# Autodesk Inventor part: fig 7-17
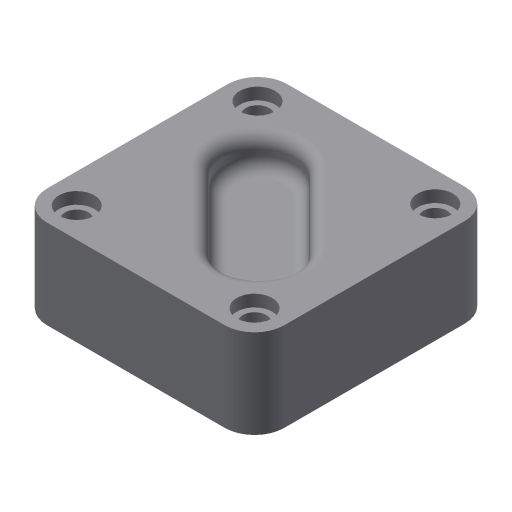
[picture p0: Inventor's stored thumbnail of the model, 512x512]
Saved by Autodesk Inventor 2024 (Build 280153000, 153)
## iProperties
Shininess: 77.0
Angle Display Precision: 2
Document Length Units: 11269
Document Angle Units: 11279
Document Time Units: 11290
Document Mass Units: 11283
Document Length Units Precision: 3
Document Angle Units Precision: 2
Created: 2001-12
Part Number: fig 7-17
Document SubType Name: Modeling
Designer: Renu Muthoo
Density: 1 g/cm^3
Material: Generic
Appearance: Default
Density: 0.0
Volumn: 0.0
Area: 0.0
PropertySet Name: Model Information
Control State: 0
Master: False
Checked Out: False
Author: Renu Muthoo
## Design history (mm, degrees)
sketch "Sketch1"
  geometry: L1 (-20, 20)-(20, 20); L2 (20, 20)-(20, -20.5); L3 (20, -20.5)-(-20, -20.5); L4 (-20, -20.5)-(-20, 20); 1 further point
  constraints: 8 end point, 2 parallel, 1 horizontal, 1 perpendicular, 1 other
  dimensions: "d0" = 40 distance of L1.start L1.end; "d1" = 40.5 distance of L3.end L1.start; "d100" = 20 distance from line of L4 point (0, 0); "d101" = 20 distance from line of L1 point (0, 0)
extrude "Extrusion1" new body sketch "Sketch1" distance "d2" = 15; taper "d3" = 0 deg
workplane "Work Plane1"
workplane "Work Plane2"
workplane "Work Plane3"
fillet "Fillet1" dims "d32" = 5
hole "Hole3" diameter "d66" = 4; stored, may be unused: countersink angle "d70" = 90 deg, drill point angle "d72" = 118 deg; dims "d64" = 10, "d65" = 10, "d67" = 6, "d68" = 6, "d69" = 2, "d71" = 8
hole "Hole4" diameter "d75" = 4; stored, may be unused: countersink angle "d79" = 90 deg, drill point angle "d81" = 118 deg; dims "d73" = 10, "d74" = 10, "d76" = 6, "d77" = 6, "d78" = 2, "d80" = 8
hole "Hole5" diameter "d84" = 4; stored, may be unused: countersink angle "d88" = 90 deg, drill point angle "d90" = 118 deg; dims "d82" = 10, "d83" = 10, "d85" = 6, "d86" = 6, "d87" = 2, "d89" = 8
hole "Hole6" diameter "d93" = 4; stored, may be unused: countersink angle "d97" = 90 deg, drill point angle "d99" = 118 deg; dims "d91" = 10, "d92" = 10, "d94" = 6, "d95" = 6, "d96" = 2, "d98" = 8
fillet "Fillet2" dims "d61" = 2
body "Solid1"
sketch "Sketch8"
  geometry: L1 (-9.844, 1.64)-(1.983, -10.187); L2 (10.469, -1.701)-(-1.358, 10.126); A1 r 6 centre (-5.601, 5.883) between (-1.358, 10.126) and (-9.844, 1.64); A2 r 6 centre (6.226, -5.944) between (1.983, -10.187) and (10.469, -1.701)
  constraints: 4 end point, 4 point on circle, 4 tangent, 2 centre point, 1 parallel
  dimensions: "d29" = 6 radius of A2
extrude "Extrusion2" cut sketch "Sketch8" distance "d30" = 5; taper "d31" = 0 deg
